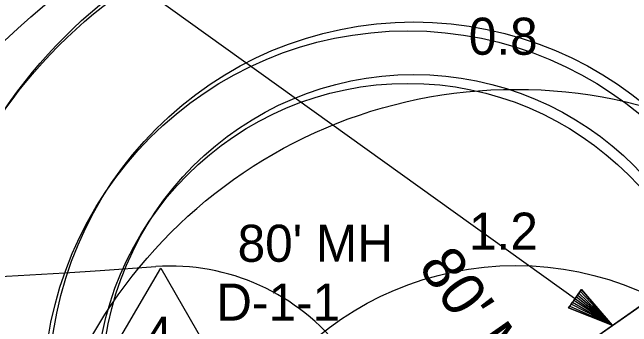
# Model space of a CAD drawing. Extents: x 1638506 to 1658005, y 834807 to 846788.
# Drawn here: x 1640888.8 to 1641089.4, y 842596.7 to 842698.3 of the extents above; entities that cross this region are included whole.
import ezdxf

# ---------------------------------------------------------------- set-up
doc = ezdxf.new("R2010")
doc.units = 0
for name, color, linetype in [('Default', 7, 'Continuous'), ('Old_Level_1', 7, 'Continuous'), ('Old_Level_2', 7, 'Continuous'), ('Old_Level_4', 7, 'Continuous'), ('Scratch_Level_0', 7, 'Continuous')]:
    doc.layers.add(name, color=color, linetype=linetype)

msp = doc.modelspace()

# ---------------------------------------------------------------- linework, layer by layer
at = {"layer": 'Default'}
for p, q in [((1640721.43, 842856.33), (1641083.08, 842597.13)), ((1641026.67, 842557.47), (1641133.66, 842632.51)), ((1641046.57, 842571.52), (1641129.92, 842630))]:
    msp.add_line(p, q, dxfattribs=at)
msp.add_lwpolyline([(1640955.44, 842583.33), (1640918.05, 842583.33), (1640936.88, 842615.59)], close=True, dxfattribs=at)
msp.add_lwpolyline([(1641071.05, 842605.75), (1641071.48, 842606.35), (1641083.08, 842597.13), (1641071.88, 842606.91), (1641072.31, 842607.52), (1641083.08, 842597.13), (1641072.74, 842608.12), (1641073.18, 842608.72), (1641083.08, 842597.13), (1641068.93, 842602.72), (1641069.33, 842603.35), (1641083.08, 842597.13), (1641069.8, 842603.92), (1641070.19, 842604.55), (1641083.08, 842597.13), (1641070.62, 842605.15), (1641073.18, 842608.72), (1641068.93, 842602.72), (1641083.08, 842597.13), (1641073.18, 842608.72)], dxfattribs=at)
at = {"layer": 'Old_Level_1'}
for centre, radius in [((1641016.92, 842574.38), 297), ((1641016.92, 842574.38), 264), ((1641016.92, 842574.38), 219), ((1641016.92, 842574.38), 160), ((1641016.92, 842574.38), 118), ((1641016.92, 842574.38), 101), ((1641295.68, 842272.71), 365)]:
    msp.add_circle(centre, radius, dxfattribs=at)
at = {"layer": 'Old_Level_2'}
msp.add_line((1640917.22, 842614.84), (1640935.25, 842616.09), dxfattribs=at)
for centre, radius, start, end in [((1640787.74, 844492.39), 1882, 251.76578, 273.94492), ((1640940.07, 842546.25), 70, 37.3323, 93.9449)]:
    msp.add_arc(centre, radius, start, end, dxfattribs=at)
at = {"layer": 'Old_Level_4'}
for radius in [365, 307, 240, 158, 101]:
    msp.add_circle((1641051.91, 842515.45), radius, dxfattribs=at)
at = {"layer": 'Scratch_Level_0'}
for radius in [297, 264, 219, 160, 118, 101]:
    msp.add_circle((1641018.82, 842577.25), radius, dxfattribs=at)

# ---------------------------------------------------------------- texts
at = {"layer": 'Default'}
for s, p in [('D-1-1', (1640954.82, 842598.63)), ('4', (1640931.7, 842587.93))]:
    msp.add_text(s, height=12, dxfattribs=at).set_placement(p)
at = {"layer": 'Old_Level_1'}
msp.add_text("80' MH", height=14, rotation=305, dxfattribs=at).set_placement((1641020.02, 842616))
at = {"layer": 'Old_Level_4'}
for s, p in [('0.8', (1641036.62, 842684.64)), ('1.2', (1641036.71, 842621.56))]:
    msp.add_text(s, height=12, dxfattribs=at).set_placement(p)
at = {"layer": 'Scratch_Level_0'}
msp.add_text("80' MH", height=12, dxfattribs=at).set_placement((1640961.76, 842617.65))

doc.saveas('drawing.dxf')
